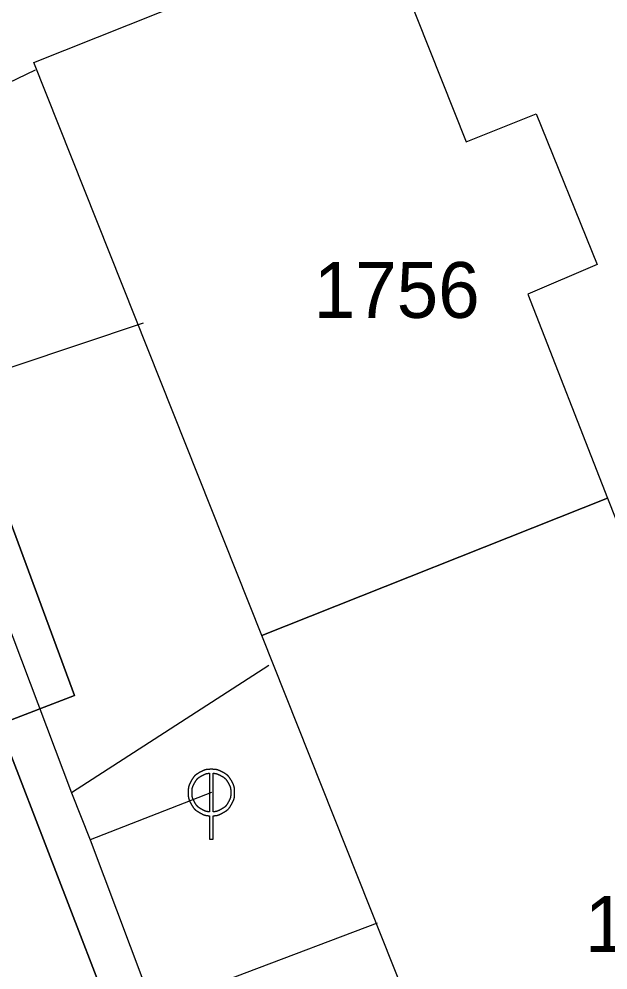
# Model space of a CAD drawing. Extents: x -562248 to -562040, y -1079385 to -1079027.
# Drawn here: x -562103.13 to -562087.3, y -1079190.52 to -1079164.97 of the extents above; entities that cross this region are included whole.
import ezdxf

# ---------------------------------------------------------------- set-up
doc = ezdxf.new("R2010")
doc.units = 0
for name, color, linetype in [('Default', 7, 'Continuous'), ('Kanalizační přípojka', 7, 'Continuous'), ('Kanalizační stoka', 7, 'Continuous'), ('Kanalizační šachta', 7, 'Continuous'), ('Parcela-polygon', 7, 'Continuous'), ('Parcela-text', 7, 'Continuous'), ('Vodovodní přípojka', 7, 'Continuous')]:
    doc.layers.add(name, color=color, linetype=linetype)

msp = doc.modelspace()

# ---------------------------------------------------------------- linework, layer by layer
at = {"layer": 'Default'}
for points in [[(-562098.268, -1079185.206), (-562098.367, -1079185.259), (-562098.445, -1079185.336), (-562098.501, -1079185.436)], [(-562098.41, -1079185.489), (-562098.364, -1079185.406), (-562098.299, -1079185.341), (-562098.216, -1079185.296)], [(-562097.96, -1079185.125), (-562098.066, -1079185.125), (-562098.168, -1079185.152), (-562098.268, -1079185.206)], [(-562098.216, -1079185.296), (-562098.145, -1079185.258), (-562098.076, -1079185.236), (-562098.011, -1079185.23)], [(-562097.652, -1079185.206), (-562097.752, -1079185.152), (-562097.854, -1079185.125), (-562097.96, -1079185.125)], [(-562097.909, -1079185.23), (-562097.842, -1079185.236), (-562097.774, -1079185.258), (-562097.704, -1079185.296)], [(-562097.704, -1079185.296), (-562097.621, -1079185.341), (-562097.556, -1079185.406), (-562097.508, -1079185.489)], [(-562097.419, -1079185.436), (-562097.475, -1079185.336), (-562097.553, -1079185.259), (-562097.652, -1079185.206)], [(-562098.501, -1079185.436), (-562098.557, -1079185.536), (-562098.585, -1079185.641), (-562098.585, -1079185.75)], [(-562098.48, -1079185.75), (-562098.48, -1079185.659), (-562098.457, -1079185.572), (-562098.41, -1079185.489)], [(-562097.508, -1079185.489), (-562097.461, -1079185.572), (-562097.438, -1079185.659), (-562097.438, -1079185.75)], [(-562097.335, -1079185.75), (-562097.335, -1079185.641), (-562097.363, -1079185.536), (-562097.419, -1079185.436)], [(-562098.585, -1079185.75), (-562098.585, -1079185.857), (-562098.557, -1079185.961), (-562098.502, -1079186.06)], [(-562098.412, -1079186.008), (-562098.457, -1079185.925), (-562098.48, -1079185.84), (-562098.48, -1079185.75)], [(-562097.438, -1079185.75), (-562097.438, -1079185.84), (-562097.46, -1079185.925), (-562097.506, -1079186.008)], [(-562097.417, -1079186.06), (-562097.362, -1079185.961), (-562097.335, -1079185.857), (-562097.335, -1079185.75)], [(-562098.502, -1079186.06), (-562098.447, -1079186.159), (-562098.369, -1079186.237), (-562098.27, -1079186.292)], [(-562098.219, -1079186.199), (-562098.302, -1079186.154), (-562098.366, -1079186.09), (-562098.412, -1079186.008)], [(-562097.506, -1079186.008), (-562097.551, -1079186.09), (-562097.616, -1079186.154), (-562097.699, -1079186.199)], [(-562097.648, -1079186.292), (-562097.548, -1079186.237), (-562097.471, -1079186.159), (-562097.417, -1079186.06)], [(-562098.27, -1079186.292), (-562098.184, -1079186.341), (-562098.098, -1079186.368), (-562098.011, -1079186.373)], [(-562098.011, -1079186.268), (-562098.08, -1079186.263), (-562098.149, -1079186.24), (-562098.219, -1079186.199)], [(-562097.699, -1079186.199), (-562097.77, -1079186.24), (-562097.84, -1079186.263), (-562097.909, -1079186.268)], [(-562097.909, -1079186.373), (-562097.822, -1079186.368), (-562097.735, -1079186.341), (-562097.648, -1079186.292)]]:
    msp.add_open_spline(points, degree=2, dxfattribs=at)
at = {"layer": 'Kanalizační přípojka'}
for points in [[(-562102.7, -1079166.35), (-562108.081, -1079168.93)], [(-562096.42, -1079182.34), (-562101.716, -1079185.754)], [(-562097.96, -1079185.75), (-562101.215, -1079187.021)]]:
    msp.add_lwpolyline(points, dxfattribs=at)
at = {"layer": 'Kanalizační stoka'}
msp.add_lwpolyline([(-562108.95, -1079166.63), (-562107.34, -1079170.89), (-562101.716, -1079185.754), (-562101.215, -1079187.021), (-562096.915, -1079198.445), (-562094.443, -1079204.981), (-562093.91, -1079206.39)], dxfattribs=at)
at = {"layer": 'Kanalizační šachta'}
for points in [[(-562098.011, -1079185.23), (-562098.011, -1079186.268)], [(-562097.909, -1079186.268), (-562097.909, -1079185.23)], [(-562098.011, -1079187), (-562097.909, -1079187), (-562097.909, -1079186.373)], [(-562098.011, -1079186.373), (-562098.011, -1079187)]]:
    msp.add_lwpolyline(points, dxfattribs=at)
at = {"layer": 'Parcela-polygon'}
for points in [[(-562074.7, -1079253.09), (-562081.96, -1079237.32), (-562088.81, -1079221.44), (-562094.66, -1079207.06), (-562098.96, -1079196.12), (-562103.67, -1079183.92), (-562101.64, -1079183.14), (-562108.26, -1079165.24), (-562109.03, -1079162.72), (-562110.57, -1079158.43), (-562113.13, -1079150.92), (-562115.47, -1079143.79), (-562118.94, -1079132.53), (-562120.22, -1079128.2), (-562121.94, -1079119.29), (-562122.55, -1079115.89), (-562122.79, -1079112.89), (-562122.92, -1079108.96), (-562122.69, -1079105.05), (-562122.05, -1079101.16)], [(-562081.378, -1079153.144), (-562109.03, -1079162.72), (-562108.26, -1079165.24), (-562101.64, -1079183.14), (-562103.67, -1079183.92), (-562098.96, -1079196.12), (-562094.66, -1079207.06), (-562088.81, -1079221.44), (-562081.96, -1079237.32), (-562074.7, -1079253.09), (-562050.734, -1079242.89)], [(-562096.6, -1079181.53), (-562102.73, -1079166.14), (-562093.43, -1079162.43), (-562091.11, -1079168.27), (-562089.23, -1079167.52), (-562087.59, -1079171.57), (-562089.45, -1079172.36), (-562087.31, -1079177.84), (-562084.66, -1079184.52)], [(-562087.15, -1079205.27), (-562088.06, -1079205.65), (-562089.73, -1079201.46), (-562091.4, -1079197.27), (-562090.48, -1079196.9), (-562096.6, -1079181.53)]]:
    msp.add_lwpolyline(points, dxfattribs=at)
for points in [[(-562091.11, -1079168.27), (-562089.23, -1079167.52), (-562087.59, -1079171.57), (-562089.45, -1079172.36), (-562087.31, -1079177.84), (-562096.6, -1079181.53), (-562102.73, -1079166.14), (-562093.43, -1079162.43)], [(-562096.6, -1079181.53), (-562087.31, -1079177.84), (-562084.66, -1079184.52), (-562082.74, -1079183.76), (-562081.12, -1079187.88), (-562082.98, -1079188.64), (-562079.54, -1079197.41), (-562089.73, -1079201.46), (-562091.4, -1079197.27), (-562090.48, -1079196.9)]]:
    msp.add_lwpolyline(points, close=True, dxfattribs=at)
at = {"layer": 'Vodovodní přípojka'}
for points in [[(-562111.609, -1079176.901), (-562111.481, -1079176.844), (-562106.696, -1079175.445), (-562099.788, -1079173.136)], [(-562105.774, -1079193.637), (-562105.675, -1079193.599), (-562104.679, -1079193.284), (-562100.5, -1079191.9), (-562093.494, -1079189.248)]]:
    msp.add_lwpolyline(points, dxfattribs=at)

# ---------------------------------------------------------------- texts
at = {"layer": 'Parcela-text'}
for s, p in [('1756', (-562095.21, -1079173)), ('1757', (-562087.92, -1079190.03))]:
    msp.add_text(s, height=1.5, dxfattribs=at).set_placement(p)

doc.saveas('drawing.dxf')
